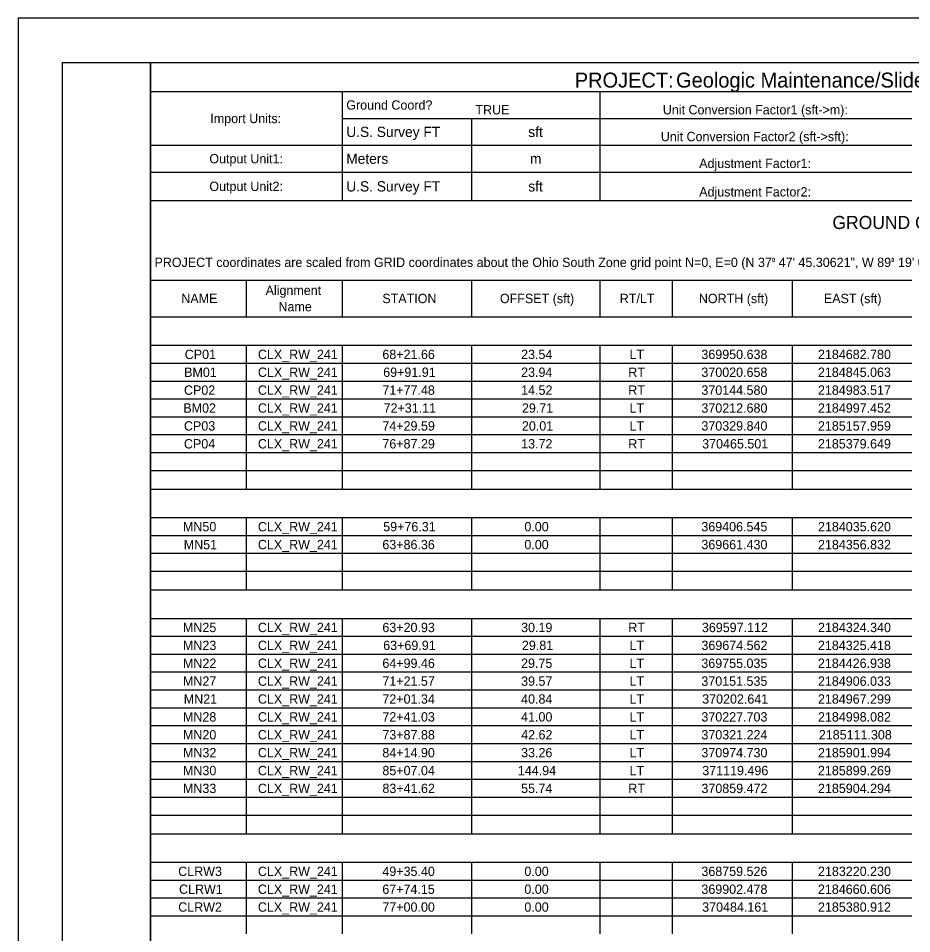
# Model space of a CAD drawing. Extents: x 0 to 680, y 0 to 440.
# Drawn here: x 0 to 202.8, y 232.3 to 440 of the extents above; entities that cross this region are included whole.
import ezdxf

# ---------------------------------------------------------------- set-up
doc = ezdxf.new("R2010")
doc.units = 0
for name, color, linetype in [('SH_Border', 7, 'Continuous'), ('SH_Cut_Line', 7, 'Continuous'), ('SH_Text', 7, 'Continuous')]:
    doc.layers.add(name, color=color, linetype=linetype)

msp = doc.modelspace()

# ---------------------------------------------------------------- linework, layer by layer
at = {"layer": 'SH_Border'}
for points in [[(10, 430), (30, 430), (30, 10), (10, 10)], [(30, 430), (670, 430), (670, 10), (30, 10)]]:
    msp.add_lwpolyline(points, close=True, dxfattribs=at)
at = {"layer": 'SH_Cut_Line'}
msp.add_lwpolyline([(0, 0), (680, 0), (680, 440), (0, 440)], close=True, dxfattribs=at)
at = {"layer": 'SH_Text'}
for p, q in [((30, 423.36), (202.84, 423.36)), ((30, 423.36), (30, 380.57)), ((73.53, 423.36), (73.53, 398.64)), ((132.01, 423.36), (132.01, 398.64)), ((73.53, 417.27), (202.84, 417.27)), ((102.86, 417.27), (102.86, 398.64)), ((30, 411.19), (132.01, 411.19)), ((132.01, 411.19), (202.84, 411.19)), ((30, 405.1), (202.84, 405.1)), ((30, 398.64), (132.01, 398.64)), ((132.01, 398.64), (202.84, 398.64)), ((30, 380.57), (202.84, 380.57)), ((30, 380.57), (30, 349.58)), ((51.77, 380.57), (51.77, 372.27)), ((73.53, 380.57), (73.53, 372.27)), ((102.86, 380.57), (102.86, 372.27)), ((132.01, 380.57), (132.01, 372.27)), ((148.42, 380.57), (148.42, 372.27)), ((175.72, 380.57), (175.72, 372.27)), ((30, 372.27), (202.84, 372.27)), ((30, 365.81), (202.84, 365.81)), ((51.77, 365.81), (51.77, 349.58)), ((73.53, 365.81), (73.53, 349.58)), ((102.86, 365.81), (102.86, 349.58)), ((132.01, 365.81), (132.01, 349.58)), ((148.42, 365.81), (148.42, 349.58)), ((175.72, 365.81), (175.72, 349.58)), ((30, 361.75), (202.84, 361.75)), ((30, 357.69), (202.84, 357.69)), ((30, 353.64), (202.84, 353.64)), ((30, 349.58), (202.84, 349.58)), ((30, 349.58), (30, 345.52)), ((51.77, 349.58), (51.77, 345.52)), ((73.53, 349.58), (73.53, 345.52)), ((102.86, 349.58), (102.86, 345.52)), ((132.01, 349.58), (132.01, 345.52)), ((148.42, 349.58), (148.42, 345.52)), ((175.72, 349.58), (175.72, 345.52)), ((30, 345.52), (202.84, 345.52)), ((30, 345.52), (30, 267.31)), ((51.77, 345.52), (51.77, 333.16)), ((73.53, 345.52), (73.53, 333.16)), ((102.86, 345.52), (102.86, 333.16)), ((132.01, 345.52), (132.01, 333.16)), ((148.42, 345.52), (148.42, 333.16)), ((175.72, 345.52), (175.72, 333.16)), ((30, 341.46), (202.84, 341.46)), ((30, 337.4), (202.84, 337.4)), ((30, 333.16), (202.84, 333.16)), ((30, 326.71), (202.84, 326.71)), ((51.77, 326.71), (51.77, 310.29)), ((73.53, 326.71), (73.53, 310.29)), ((102.86, 326.71), (102.86, 310.29)), ((132.01, 326.71), (132.01, 310.29)), ((148.42, 326.71), (148.42, 310.29)), ((175.72, 326.71), (175.72, 310.29)), ((30, 322.65), (202.84, 322.65)), ((30, 318.59), (202.84, 318.59)), ((30, 314.53), (202.84, 314.53)), ((30, 310.29), (202.84, 310.29)), ((30, 303.83), (202.84, 303.83)), ((51.77, 303.83), (51.77, 267.31)), ((73.53, 303.83), (73.53, 267.31)), ((102.86, 303.83), (102.86, 267.31)), ((132.01, 303.83), (132.01, 267.31)), ((148.42, 303.83), (148.42, 267.31)), ((175.72, 303.83), (175.72, 267.31)), ((30, 299.78), (202.84, 299.78)), ((30, 295.72), (202.84, 295.72)), ((30, 291.66), (202.84, 291.66)), ((30, 287.6), (202.84, 287.6)), ((30, 283.54), (202.84, 283.54)), ((30, 279.49), (202.84, 279.49)), ((30, 275.43), (202.84, 275.43)), ((30, 271.37), (202.84, 271.37)), ((30, 267.31), (202.84, 267.31)), ((30, 267.31), (30, 263.25)), ((51.77, 267.31), (51.77, 263.25)), ((73.53, 267.31), (73.53, 263.25)), ((102.86, 267.31), (102.86, 263.25)), ((132.01, 267.31), (132.01, 263.25)), ((148.42, 267.31), (148.42, 263.25)), ((175.72, 267.31), (175.72, 263.25)), ((30, 263.25), (202.84, 263.25)), ((30, 263.25), (30, 240.38)), ((51.77, 263.25), (51.77, 254.95)), ((73.53, 263.25), (73.53, 254.95)), ((102.86, 263.25), (102.86, 254.95)), ((132.01, 263.25), (132.01, 254.95)), ((148.42, 263.25), (148.42, 254.95)), ((175.72, 263.25), (175.72, 254.95)), ((30, 259.2), (202.84, 259.2)), ((30, 254.95), (202.84, 254.95)), ((30, 248.5), (202.84, 248.5)), ((51.77, 248.5), (51.77, 240.38)), ((73.53, 248.5), (73.53, 240.38)), ((102.86, 248.5), (102.86, 240.38)), ((132.01, 248.5), (132.01, 240.38)), ((148.42, 248.5), (148.42, 240.38)), ((175.72, 248.5), (175.72, 240.38)), ((30, 244.44), (202.84, 244.44)), ((30, 240.38), (202.84, 240.38)), ((30, 240.38), (30, 236.32)), ((51.77, 240.38), (51.77, 236.32)), ((73.53, 240.38), (73.53, 236.32)), ((102.86, 240.38), (102.86, 236.32)), ((132.01, 240.38), (132.01, 236.32)), ((148.42, 240.38), (148.42, 236.32)), ((175.72, 240.38), (175.72, 236.32)), ((30, 236.32), (202.84, 236.32)), ((30, 236.32), (30, 232.26)), ((51.77, 236.32), (51.77, 232.26)), ((73.53, 236.32), (73.53, 232.26)), ((102.86, 236.32), (102.86, 232.26)), ((132.01, 236.32), (132.01, 232.26)), ((148.42, 236.32), (148.42, 232.26)), ((175.72, 236.32), (175.72, 232.26))]:
    msp.add_line(p, q, dxfattribs=at)

# ---------------------------------------------------------------- texts
for s, height, p in [('PROJECT:', 3.394, (126.34, 424.28)), ('Geologic Maintenance/Slide Repair', 3.394, (149.34, 424.28)), ('Ground Coord?', 2.1212, (74.46, 419.26)), ('TRUE', 2.121, (103.78, 418.19)), ('Unit Conversion Factor1 (sft->m):', 2.1212, (146.33, 418.19)), ('Import Units:', 2.1212, (43.6, 416.21)), ('sft', 2.333, (115.78, 413.06)), ('U.S. Survey FT', 2.3333, (74.46, 413.06)), ('Unit Conversion Factor2 (sft->sft):', 2.1212, (145.88, 412.11)), ('Output Unit1:', 2.1212, (43.38, 407.08)), ('Meters', 2.333, (74.46, 406.98)), ('m', 2.33, (116.18, 406.98)), ('Adjustment Factor1:', 2.1212, (154.59, 406.02)), ('Output Unit2:', 2.1212, (43.38, 400.81)), ('U.S. Survey FT', 2.3333, (74.46, 400.7)), ('sft', 2.333, (115.78, 400.7)), ('Adjustment Factor2:', 2.1212, (154.59, 399.56)), ('GROUND COORDINATES - U.S. Survey FT', 2.9697, (184.84, 392.18)), ('PROJECT coordinates are scaled from GRID coordinates about the Ohio South Zone grid point N=0, E=0 (N 37⁰ 47\' 45.30621", W 89⁰ 19\' 00.02517")', 2.12122, (30.92, 383.56)), ('Alignment ', 2.121, (56.15, 377.21)), ('NAME', 2.121, (37.02, 375.36)), ('STATION', 2.121, (82.65, 375.36)), ('OFFSET (sft)', 2.1212, (109.35, 375.36)), ('RT/LT', 2.121, (136.56, 375.36)), ('NORTH (sft)', 2.1212, (154.51, 375.36)), ('EAST (sft)', 2.121, (182.9, 375.36)), ('Name', 2.121, (59.07, 373.5)), ('CP01', 2.121, (37.79, 362.67)), ('CLX_RW_241', 2.121, (54.4, 362.67)), ('68+21.66', 2.121, (82.66, 362.67)), ('23.54', 2.121, (114.16, 362.67)), ('LT', 2.121, (138.78, 362.67)), ('369950.638', 2.121, (155.09, 362.67)), ('2184682.780', 2.1212, (181.56, 362.67)), ('BM01', 2.121, (37.65, 358.62)), ('CLX_RW_241', 2.121, (54.4, 358.62)), ('69+91.91', 2.121, (82.85, 358.62)), ('23.94', 2.121, (114.16, 358.62)), ('RT', 2.121, (138.49, 358.62)), ('370020.658', 2.121, (155.09, 358.62)), ('2184845.063', 2.1212, (181.55, 358.62)), ('CP02', 2.121, (37.62, 354.56)), ('CLX_RW_241', 2.121, (54.4, 354.56)), ('71+77.48', 2.121, (82.66, 354.56)), ('14.52', 2.121, (114.17, 354.56)), ('RT', 2.121, (138.49, 354.56)), ('370144.580', 2.121, (155.09, 354.56)), ('2184983.517', 2.1212, (181.55, 354.56)), ('BM02', 2.121, (37.47, 350.5)), ('CLX_RW_241', 2.121, (54.4, 350.5)), ('72+31.11', 2.121, (82.94, 350.5)), ('29.71', 2.121, (114.34, 350.5)), ('LT', 2.121, (138.78, 350.5)), ('370212.680', 2.121, (155.09, 350.5)), ('2184997.452', 2.1212, (181.56, 350.5)), ('CP03', 2.121, (37.61, 346.44)), ('CLX_RW_241', 2.121, (54.4, 346.44)), ('74+29.59', 2.121, (82.66, 346.44)), ('20.01', 2.121, (114.34, 346.44)), ('LT', 2.121, (138.78, 346.44)), ('370329.840', 2.121, (155.09, 346.44)), ('2185157.959', 2.1212, (181.55, 346.44)), ('CP04', 2.121, (37.61, 342.38)), ('CLX_RW_241', 2.121, (54.4, 342.38)), ('76+87.29', 2.121, (82.66, 342.38)), ('13.72', 2.121, (114.17, 342.38)), ('RT', 2.121, (138.49, 342.38)), ('370465.501', 2.121, (155.27, 342.38)), ('2185379.649', 2.1212, (181.55, 342.38)), ('MN50', 2.121, (37.39, 323.57)), ('CLX_RW_241', 2.121, (54.4, 323.57)), ('59+76.31', 2.121, (82.85, 323.57)), ('0.00', 2.121, (114.9, 323.57)), ('369406.545', 2.121, (155.08, 323.57)), ('2184035.620', 2.1212, (181.56, 323.57)), ('MN51', 2.121, (37.57, 319.51)), ('CLX_RW_241', 2.121, (54.4, 319.51)), ('63+86.36', 2.121, (82.66, 319.51)), ('0.00', 2.121, (114.9, 319.51)), ('369661.430', 2.121, (155.09, 319.51)), ('2184356.832', 2.1212, (181.56, 319.51)), ('MN25', 2.121, (37.38, 300.7)), ('CLX_RW_241', 2.121, (54.4, 300.7)), ('63+20.93', 2.121, (82.66, 300.7)), ('30.19', 2.121, (114.16, 300.7)), ('RT', 2.121, (138.49, 300.7)), ('369597.112', 2.121, (155.2, 300.7)), ('2184324.340', 2.1212, (181.56, 300.7)), ('MN23', 2.121, (37.39, 296.64)), ('CLX_RW_241', 2.121, (54.4, 296.64)), ('63+69.91', 2.121, (82.85, 296.64)), ('29.81', 2.121, (114.34, 296.64)), ('LT', 2.121, (138.78, 296.64)), ('369674.562', 2.121, (155.1, 296.64)), ('2184325.418', 2.1212, (181.55, 296.64)), ('MN22', 2.121, (37.4, 292.58)), ('CLX_RW_241', 2.121, (54.4, 292.58)), ('64+99.46', 2.121, (82.66, 292.58)), ('29.75', 2.121, (114.15, 292.58)), ('LT', 2.121, (138.78, 292.58)), ('369755.035', 2.121, (155.08, 292.58)), ('2184426.938', 2.1212, (181.55, 292.58)), ('MN27', 2.121, (37.39, 288.52)), ('CLX_RW_241', 2.121, (54.4, 288.52)), ('71+21.57', 2.121, (82.66, 288.52)), ('39.57', 2.121, (114.16, 288.52)), ('LT', 2.121, (138.78, 288.52)), ('370151.535', 2.121, (155.08, 288.52)), ('2184906.033', 2.1212, (181.55, 288.52)), ('MN21', 2.121, (37.57, 284.47)), ('CLX_RW_241', 2.121, (54.4, 284.47)), ('72+01.34', 2.121, (82.66, 284.47)), ('40.84', 2.121, (114.16, 284.47)), ('LT', 2.121, (138.78, 284.47)), ('370202.641', 2.121, (155.27, 284.47)), ('2184967.299', 2.1212, (181.55, 284.47)), ('MN28', 2.121, (37.39, 280.41)), ('CLX_RW_241', 2.121, (54.4, 280.41)), ('72+41.03', 2.121, (82.66, 280.41)), ('41.00', 2.121, (114.16, 280.41)), ('LT', 2.121, (138.78, 280.41)), ('370227.703', 2.121, (155.09, 280.41)), ('2184998.082', 2.1212, (181.56, 280.41)), ('MN20', 2.121, (37.39, 276.35)), ('CLX_RW_241', 2.121, (54.4, 276.35)), ('73+87.88', 2.121, (82.66, 276.35)), ('42.62', 2.121, (114.17, 276.35)), ('LT', 2.121, (138.78, 276.35)), ('370321.224', 2.121, (155.09, 276.35)), ('2185111.308', 2.1212, (181.75, 276.35)), ('MN32', 2.121, (37.4, 272.29)), ('CLX_RW_241', 2.121, (54.4, 272.29)), ('84+14.90', 2.121, (82.66, 272.29)), ('33.26', 2.121, (114.16, 272.29)), ('LT', 2.121, (138.78, 272.29)), ('370974.730', 2.121, (155.09, 272.29)), ('2185901.994', 2.1212, (181.56, 272.29)), ('MN30', 2.121, (37.39, 268.23)), ('CLX_RW_241', 2.121, (54.4, 268.23)), ('85+07.04', 2.121, (82.66, 268.23)), ('144.94', 2.121, (113.42, 268.23)), ('LT', 2.121, (138.78, 268.23)), ('371119.496', 2.121, (155.29, 268.23)), ('2185899.269', 2.1212, (181.55, 268.23)), ('MN33', 2.121, (37.39, 264.18)), ('CLX_RW_241', 2.121, (54.4, 264.18)), ('83+41.62', 2.121, (82.67, 264.18)), ('55.74', 2.121, (114.16, 264.18)), ('RT', 2.121, (138.49, 264.18)), ('370859.472', 2.121, (155.1, 264.18)), ('2185904.294', 2.1212, (181.56, 264.18)), ('CLRW3', 2.121, (36.3, 245.36)), ('CLX_RW_241', 2.121, (54.4, 245.36)), ('49+35.40', 2.121, (82.66, 245.36)), ('0.00', 2.121, (114.9, 245.36)), ('368759.526', 2.121, (155.09, 245.36)), ('2183220.230', 2.1212, (181.56, 245.36)), ('CLRW1', 2.121, (36.49, 241.3)), ('CLX_RW_241', 2.121, (54.4, 241.3)), ('67+74.15', 2.121, (82.65, 241.3)), ('0.00', 2.121, (114.9, 241.3)), ('369902.478', 2.121, (155.09, 241.3)), ('2184660.606', 2.1212, (181.55, 241.3)), ('CLRW2', 2.121, (36.31, 237.25)), ('CLX_RW_241', 2.121, (54.4, 237.25)), ('77+00.00', 2.121, (82.66, 237.25)), ('0.00', 2.121, (114.9, 237.25)), ('370484.161', 2.121, (155.27, 237.25)), ('2185380.912', 2.1212, (181.56, 237.25))]:
    msp.add_text(s, height=height, dxfattribs=at).set_placement(p)

doc.saveas('drawing.dxf')
